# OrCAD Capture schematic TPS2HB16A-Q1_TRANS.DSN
size D; title: TPS2HB16A-Q1 40-V, 16-mOhm Dual-Channel Smart High-; rev: 1.0; note: Datasheet: SLVSDV7C     EVM: SLVUBD4B; note: Side Switch
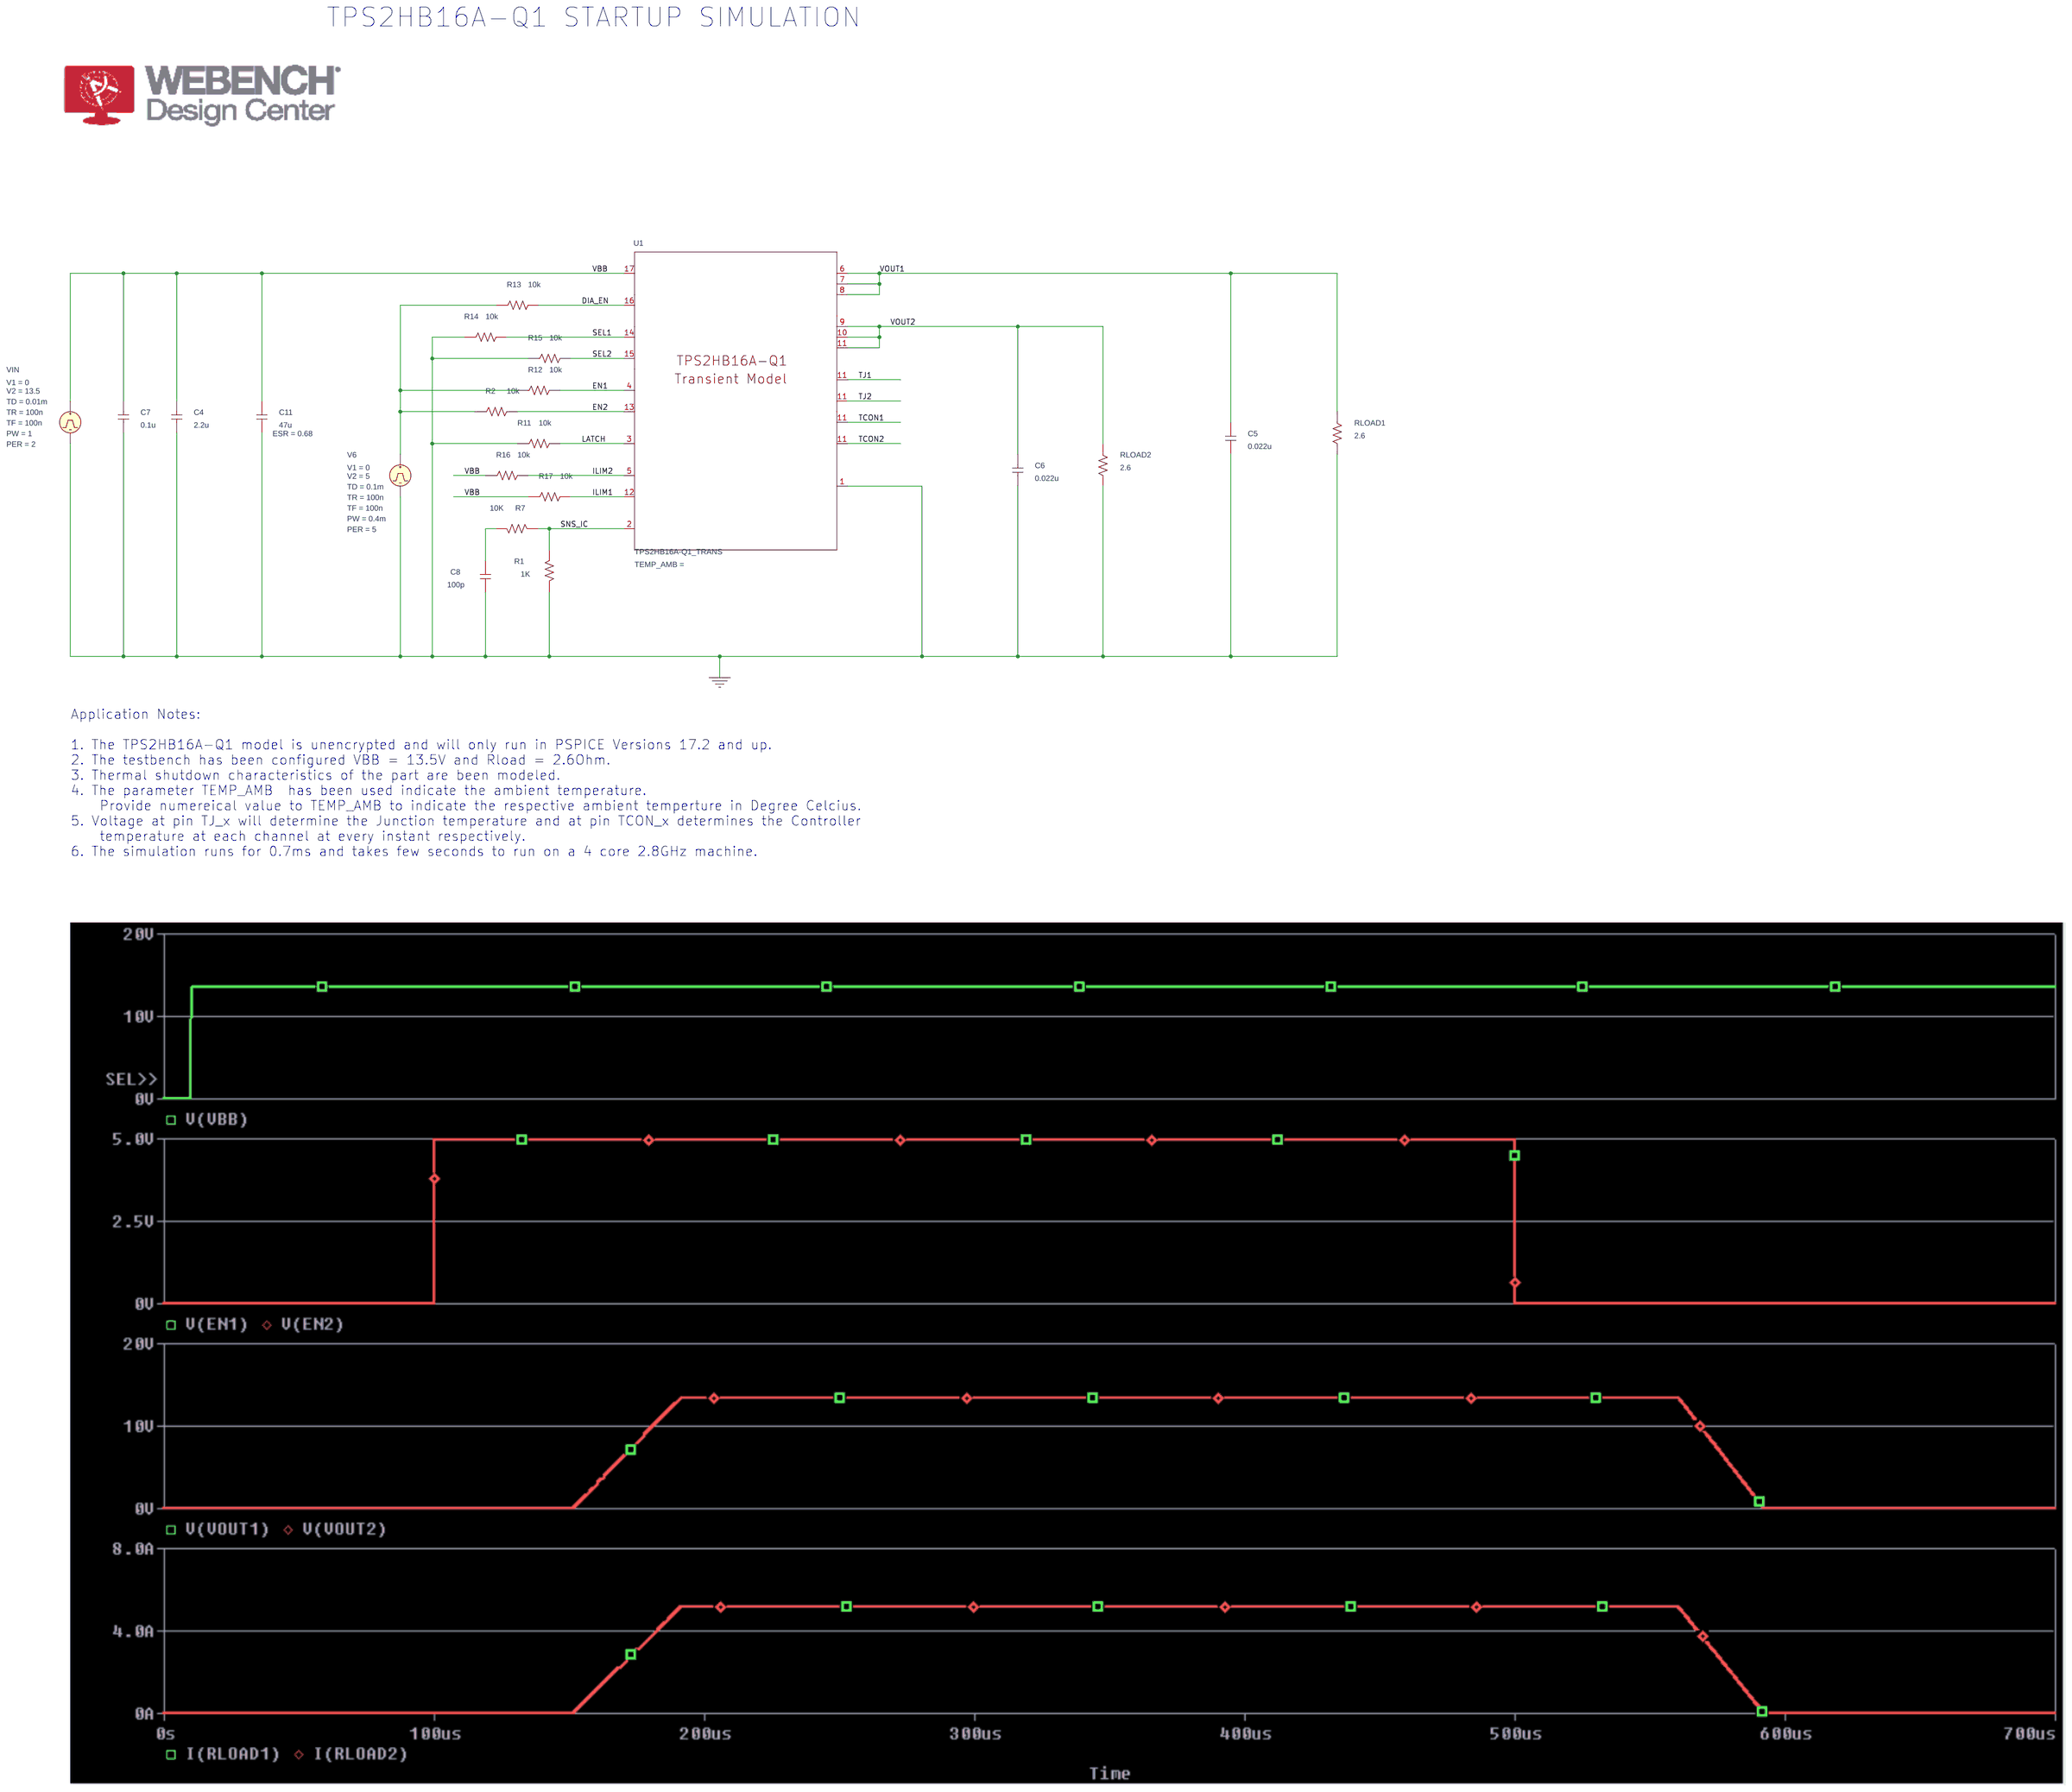
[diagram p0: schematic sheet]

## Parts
C4  2.2u  [RAD/CK05]
C5  0.022u  [RAD/CK05]
C6  0.022u  [RAD/CK05]
C7  0.1u  [RAD/CK05]
C8  100p  [RAD/CK05]
C11  47u  [RAD/CK05]
R1  1K  [AX/RC05]
R2  10k  [AX/RC05]
R7  10K  [AX/RC05]
R11  10k  [AX/RC05]
R12  10k  [AX/RC05]
R13  10k  [AX/RC05]
R14  10k  [AX/RC05]
R15  10k  [AX/RC05]
R16  10k  [AX/RC05]
R17  10k  [AX/RC05]
RLOAD1  2.6  [AX/RC05]
RLOAD2  2.6  [AX/RC05]
U1  TPS2HB16A-Q1_TRANS  [PWP0016M_N]
V6  VPULSE
VIN  VPULSE

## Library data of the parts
C4-C8 = C
C11 = C: AppProp: InductiveSlave:;SRF:;PrevCap:47u;PrevESL:; ESR: 0.68
R1 R2 R7 R11-R17 RLOAD1 RLOAD2 = R
U1 = TPS2HB16A-Q1_TRANS
V6 = VPULSE: PER: 5; PW: 0.4m; TD: 0.1m; TF: 100n; TR: 100n; V1: 0; V2: 5
VIN = VPULSE: PER: 2; PW: 1; TD: 0.01m; TF: 100n; TR: 100n; V1: 0; V2: 13.5

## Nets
0: C4.2 C5.2 C6.2 C7.2 C8.2 C11.1 R1.1 R11.1 R14.1 R15.1 RLOAD1.2 RLOAD2.2 U1.1(GND) V6.2(-) VIN.2(-)
DIA_EN: R13.2 U1.16(DIA_EN)
EN1: R12.2 U1.4(EN1)
EN2: R2.2 U1.13(EN2)
ILIM1: R17.2 U1.12(ILIM2)
ILIM2: R16.2 U1.5(ILIM1)
LATCH: R11.2 U1.3(LATCH)
SEL1: R14.2 U1.14(SEL1)
SEL2: R15.2 U1.15(SEL2)
SNS_IC: R1.2 R7.1 U1.2(SNS)
TCON1: C6.1 RLOAD2.1 U1.9(VOUT2_0) U1.10(VOUT2_1) U1.11(TCON_2)
VBB: C4.1 C7.1 C11.2 R16.1 R17.1 U1.17(VBB) VIN.1(+)
VOUT1: C5.1 RLOAD1.1 U1.6(VOUT1_0) U1.7(VOUT1_1) U1.8(VOUT1_2)
N16786789: R2.1 R12.1 R13.1 V6.1(+)
N16787126: C8.1 R7.2

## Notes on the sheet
- TPS2HB16A-Q1 STARTUP SIMULATION
- Application Notes:
  1. The TPS2HB16A-Q1 model is unencrypted and will only run in PSPICE Versions 17.2 and up.
  2. The testbench has been configured VBB = 13.5V and Rload = 2.6Ohm.
  3. Thermal shutdown characteristics of the part are been modeled.
  4. The parameter TEMP_AMB  has been used indicate the ambient temperature.
      Provide numereical value to TEMP_AMB to indicate the respective ambient temperture in Degree Celcius.
  5. Voltage at pin TJ_x will determine the Junction temperature and at pin TCON_x determines the Controller
      temperature at each channel at every instant respectively.
  6. The simulation runs for 0.7ms and takes few seconds to run on a 4 core 2.8GHz machine.
